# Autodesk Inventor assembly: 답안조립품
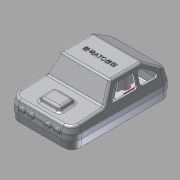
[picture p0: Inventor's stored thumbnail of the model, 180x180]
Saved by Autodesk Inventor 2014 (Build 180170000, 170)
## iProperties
Created: 2015-05
Part Number: 답안조립품
Document SubType Name: Assembly
Designer: Administrator
Author: Administrator
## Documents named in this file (22)
- C:\Documents and Settings\Administrator\바탕 화면\2015.05.23\450508V1038\답안조립품.iam
- C:\Documents and Settings\Administrator\바탕 화면\2015.05.23\450508V1038\본체.ipt
- C:\Documents and Settings\Administrator\바탕 화면\2015.05.23\450508V1038\M4x10.ipt
- C:\Documents and Settings\Administrator\바탕 화면\2015.05.23\450508V1038\바퀴.ipt
- C:\Documents and Settings\Administrator\바탕 화면\2015.05.23\450508V1038\바퀴고정부.ipt
- C:\Documents and Settings\Administrator\바탕 화면\2015.05.23\450508V1038\커버.ipt
- C:\Documents and Settings\Administrator\바탕 화면\2015.05.23\450508V1038\바퀴고정부_MIR.ipt
- C:\Documents and Settings\Administrator\바탕 화면\2015.05.23\450508V1038\바퀴고정부_MIR1.ipt
- C:\Documents and Settings\Administrator\바탕 화면\2015.05.23\450508V1038\바퀴고정부_MIR_MIR.ipt
- C:\Documents and Settings\Administrator\바탕 화면\2015.05.23\450508V1038\바퀴_MIR.ipt
- C:\Documents and Settings\Administrator\바탕 화면\2015.05.23\450508V1038\바퀴_MIR1.ipt
- C:\Documents and Settings\Administrator\바탕 화면\2015.05.23\450508V1038\바퀴_MIR_MIR.ipt
- C:\Documents and Settings\Administrator\바탕 화면\2015.05.23\450508V1038\M2x4.ipt
- C:\Documents and Settings\Administrator\바탕 화면\2015.05.23\450508V1038\M2x4_MIR.ipt
- C:\Documents and Settings\Administrator\바탕 화면\2015.05.23\450508V1038\M2x4_MIR1.ipt
- C:\Documents and Settings\Administrator\바탕 화면\2015.05.23\450508V1038\M2x4_MIR_MIR.ipt
- C:\Documents and Settings\Administrator\바탕 화면\2015.05.23\450508V1038\M2x4_MIR2.ipt
- C:\Documents and Settings\Administrator\바탕 화면\2015.05.23\450508V1038\M2x4_MIR3.ipt
- C:\Documents and Settings\Administrator\바탕 화면\2015.05.23\450508V1038\M2x4_MIR2_MIR.ipt
- C:\Documents and Settings\Administrator\바탕 화면\2015.05.23\450508V1038\M2x4_MIR2_MIR_MIR.ipt
- C:\Documents and Settings\Administrator\바탕 화면\2015.05.23\450508V1038\M2x4_MIR2_MIR_MIR1.ipt
- C:\Documents and Settings\Administrator\바탕 화면\2015.05.23\450508V1038\M2x4_MIR2_MIR_MIR_MIR.ipt
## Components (17 placed, 11 different names)
1. M4x10:1
2. M4x10:2
3. M4x10:3
4. M4x10:4
5. M2x4:1
6. M2x4_MIR:1
7. M2x4_MIR1:1
8. M2x4_MIR_MIR:1
9. M2x4:2
10. M2x4:3
11. M2x4_MIR2:1
12. M2x4_MIR3:1
13. M2x4_MIR2_MIR:1
14. M2x4_MIR2_MIR:2
15. M2x4_MIR2_MIR_MIR:1
16. M2x4_MIR2_MIR_MIR1:1
17. M2x4_MIR2_MIR_MIR_MIR:1
